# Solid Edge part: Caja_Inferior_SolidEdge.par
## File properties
Author: jonat
Template: ISO Metric Part.par
Last saved by: Will Familia
Revision: 4
Application: Solid Edge
Username: jonat
Densidad: 1385.000 kg/m^3
Precisión: 0.990
Material: PVC
Estilo de cara: Tan
Estilo de relleno: ANSI34(Plastic)
Estilo virtual: ANSI34(Plastic)
Grupos: Non-metals\Plastics
NombreDeBiblioteca: Materials
Coef. of Thermal Exp: 9e-05
Thermal Conductivity: 1.5
Specific Heat: 0.0
Modulus of Elasticity: 2757903000.0
Poisson's Ratio: 0.4
Yield Stress: 6894757.0
Ultimate Stress: 0.0
Elongation: 0.0
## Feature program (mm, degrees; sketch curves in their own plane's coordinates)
sketch for "unnamed Protrusion 1" plane through (0, 0, 0) normal (0, 0, 1) x-axis (1, 0, 0)
  line (53.5, -43.85) -> (53.5, 43.85)
  line (53.5, 43.85) -> (-53.5, 43.85)
  line (-53.5, 43.85) -> (-53.5, -43.85)
  line (-53.5, -43.85) -> (53.5, -43.85)
extrude "unnamed Protrusion 1" add finite 15 along +normal
sketch for "Corte_1" plane through (0, -43.85, 7.5) normal (0, -1, 0) x-axis (1, 0, 0)
  line (7.5, -2.5) -> (-7.5, -2.5)
  line (-7.5, -2.5) -> (-7.5, -12.5)
  line (-7.5, -12.5) -> (7.5, -12.5)
  line (7.5, -12.5) -> (7.5, -2.5)
extrude "Corte_1" cut finite 19 along -normal
sketch for "Corte_2" plane through (53.5, 0, 7.5) normal (1, 0, 0) x-axis (0, 1, 0)
  line (12.5, -2.5) -> (-12.5, -2.5)
  line (-12.5, -2.5) -> (-12.5, -12.5)
  line (-12.5, -12.5) -> (12.5, -12.5)
  line (12.5, -12.5) -> (12.5, -2.5)
extrude "Corte_2" cut finite 125.4573 along -normal
sketch for "Corte_3" plane through (0, 0, 15) normal (0, 0, 1) x-axis (1, 0, 0)
  line (51.1, -41.5) -> (51.1, 41.5)
  line (51.1, 41.5) -> (-51.1, 41.5)
  line (-51.1, 41.5) -> (-51.1, -41.5)
  line (-51.1, -41.5) -> (51.1, -41.5)
extrude "Corte_3" cut finite 8 along -normal
sketch for "ProtrusiónExtruida_2" #1 plane through (0, 0, 7) normal (0, 0, 1) x-axis (1, 0, 0)
  circle centre (-42.5, -25) radius 2.2
sketch for "ProtrusiónExtruida_2" #2 plane through (0, 0, 7) normal (0, 0, 1) x-axis (1, 0, 0)
  circle centre (42.5, 25) radius 2.2
extrude "ProtrusiónExtruida_2" add finite 7 along +normal
sketch for "Corte_4" #1 plane through (0, 0, 7) normal (0, 0, 1) x-axis (1, 0, 0)
  line (7.5, -41.5) -> (7.5, -24.85)
  line (7.5, -24.85) -> (6, -24.85)
  line (6, -24.85) -> (6, -41.5)
  line (6, -41.5) -> (7.5, -41.5)
sketch for "Corte_4" #2 plane through (0, 0, 7) normal (0, 0, 1) x-axis (1, 0, 0)
  line (-6, -24.85) -> (-6, -41.5)
  line (-6, -41.5) -> (-7.5, -41.5)
  line (-7.5, -41.5) -> (-7.5, -24.85)
  line (-7.5, -24.85) -> (-6, -24.85)
extrude "Corte_4" cut finite 21 along -normal
sketch for "Corte_5" #1 plane through (0, 0, 7) normal (0, 0, 1) x-axis (1, 0, 0)
  line (-51.1, 12.5) -> (-21.1, 12.5)
  line (-21.1, 12.5) -> (-21.1, 9.5)
  line (-21.1, 9.5) -> (-51.1, 9.5)
  line (-51.1, 9.5) -> (-51.1, 12.5)
sketch for "Corte_5" #2 plane through (0, 0, 7) normal (0, 0, 1) x-axis (1, 0, 0)
  line (51.1, 12.5) -> (21.1, 12.5)
  line (21.1, 12.5) -> (21.1, 9.5)
  line (21.1, 9.5) -> (51.1, 9.5)
  line (51.1, 9.5) -> (51.1, 12.5)
extrude "Corte_5" cut finite 84 along -normal
sketch for "Corte_6" #1 plane through (-42.5, -25, 14) normal (0, 0, 1) x-axis (1, 0, 0)
  circle centre (0, 0) radius 1.2
sketch for "Corte_6" #2 plane through (-42.5, -25, 14) normal (0, 0, 1) x-axis (1, 0, 0)
  circle centre (85, 50) radius 1.2
extrude "Corte_6" cut finite 5.5 along -normal
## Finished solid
Body 1: solid body, 33 faces, 98 edges, 60 vertices.
  Faces by surface: plane 29, cylinder 4
  Edges by curve: line 90, circle 8
Bounding box of the edges (mm): 107.000 x 87.700 x 15.000, from (-53.5, -43.85, 0) to (53.5, 43.85, 15).
Cylindrical faces by radius (mm): R1.2 x2, R2.2 x2
Planar faces by outward normal: +x 5, +y 5, +z 6, -x 5, -y 4, -z 4
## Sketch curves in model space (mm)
circle centre (42.5, 25, 14) radius 1.2
circle centre (-42.5, -25, 14) radius 1.2
line (21.1, 12.5, 7) -> (21.1, 9.5, 7)
line (21.1, 9.5, 7) -> (51.1, 9.5, 7)
line (51.1, 9.5, 7) -> (51.1, 12.5, 7)
line (51.1, 12.5, 7) -> (21.1, 12.5, 7)
line (-21.1, 12.5, 7) -> (-21.1, 9.5, 7)
line (-21.1, 9.5, 7) -> (-51.1, 9.5, 7)
line (-51.1, 9.5, 7) -> (-51.1, 12.5, 7)
line (-51.1, 12.5, 7) -> (-21.1, 12.5, 7)
line (-6, -24.85, 7) -> (-6, -41.5, 7)
line (-6, -41.5, 7) -> (-7.5, -41.5, 7)
line (-7.5, -41.5, 7) -> (-7.5, -24.85, 7)
line (-7.5, -24.85, 7) -> (-6, -24.85, 7)
line (6, -24.85, 7) -> (6, -41.5, 7)
line (6, -41.5, 7) -> (7.5, -41.5, 7)
line (7.5, -41.5, 7) -> (7.5, -24.85, 7)
line (7.5, -24.85, 7) -> (6, -24.85, 7)
circle centre (-42.5, -25, 7) radius 2.2
circle centre (42.5, 25, 7) radius 2.2
line (51.1, -41.5, 15) -> (51.1, 41.5, 15)
line (51.1, 41.5, 15) -> (-51.1, 41.5, 15)
line (-51.1, 41.5, 15) -> (-51.1, -41.5, 15)
line (-51.1, -41.5, 15) -> (51.1, -41.5, 15)
line (53.5, 12.5, -5) -> (53.5, 12.5, 5)
line (53.5, 12.5, 5) -> (53.5, -12.5, 5)
line (53.5, -12.5, 5) -> (53.5, -12.5, -5)
line (53.5, -12.5, -5) -> (53.5, 12.5, -5)
line (7.5, -43.85, -5) -> (7.5, -43.85, 5)
line (7.5, -43.85, 5) -> (-7.5, -43.85, 5)
line (-7.5, -43.85, 5) -> (-7.5, -43.85, -5)
line (-7.5, -43.85, -5) -> (7.5, -43.85, -5)
line (53.5, -43.85, 0) -> (53.5, 43.85, 0)
line (53.5, 43.85, 0) -> (-53.5, 43.85, 0)
line (-53.5, 43.85, 0) -> (-53.5, -43.85, 0)
line (-53.5, -43.85, 0) -> (53.5, -43.85, 0)
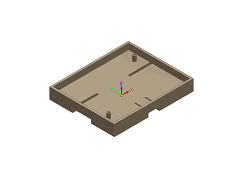
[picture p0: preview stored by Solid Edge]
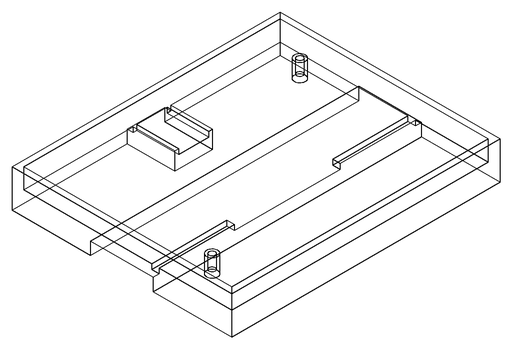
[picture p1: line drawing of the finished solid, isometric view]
